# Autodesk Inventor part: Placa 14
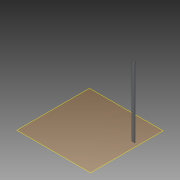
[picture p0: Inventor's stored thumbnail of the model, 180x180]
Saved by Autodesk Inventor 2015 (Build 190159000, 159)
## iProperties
Created: 2015-04
Part Number: Placa 14
Material: Generic
Document SubType Name: Modeling
Designer: suporte
Density: 1 g/cm^3
Appearance: Default
Author: suporte
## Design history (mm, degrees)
workplane "Work Plane1"
sketch "Sketch1"
  geometry: L1 (825, 317.5)-(812.5, 317.5) reference; L2 (825, 518.558)-(825, 317.5) reference; L3 (912.5, 317.5)-(900, 317.5) reference; L4 (900, 317.5)-(900, 551.158) reference; L5 (830.6, 330)-(825.6, 330) reference; L6 (825.6, 330)-(900, 330); L7 (900, 330)-(900, 317.5); L8 (900, 317.5)-(825.6, 317.5); L9 (825.6, 317.5)-(825.6, 330); 1 further point
  constraints: 8 end point, 2 parallel, 1 horizontal, 1 perpendicular
  node "Reference1"
  node "Reference2"
  node "Reference3"
  node "Reference4"
  node "Reference5"
workplane "Work Plane2"
extrude "Extrusion1" new body sketch "Sketch1" distance "d0" = 1900; taper "d1" = 0 deg
body "Solid1"
